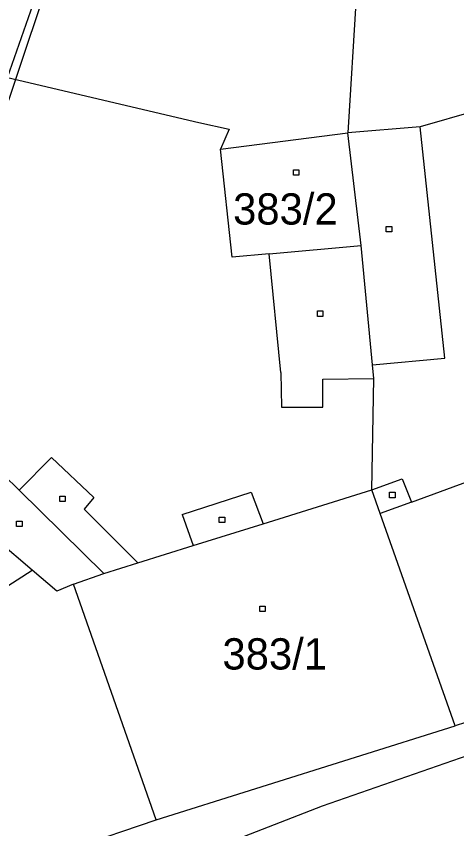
# Model space of a CAD drawing. Extents: x -711879 to -711361, y -1048782 to -1048177.
# Drawn here: x -711623.84 to -711599.87, y -1048524.94 to -1048480.75 of the extents above; entities that cross this region are included whole.
import ezdxf

# ---------------------------------------------------------------- set-up
doc = ezdxf.new("R2010")
doc.units = 0
for name, color, linetype in [('kresba', 7, 'Continuous'), ('Vrstva 1', 7, 'Continuous'), ('Vrstva 15', 7, 'Continuous'), ('Vrstva 2', 7, 'Continuous'), ('Vrstva 25', 7, 'Continuous'), ('Vrstva 46', 7, 'Continuous')]:
    doc.layers.add(name, color=color, linetype=linetype)

msp = doc.modelspace()

# ---------------------------------------------------------------- linework, layer by layer
at = {"layer": 'kresba'}
msp.add_line((-711627.89, -1048496.13), (-711612.41, -1048450.08), dxfattribs=at)
at = {"layer": 'Vrstva 1'}
for p, q in [((-711624.32, -1048484.08), (-711615.16, -1048458.11)), ((-711604.27, -1048461.61), (-711605.79, -1048487.1)), ((-711624.32, -1048484.08), (-711613.91, -1048486.53)), ((-711593.36, -1048484.32), (-711601.86, -1048486.76)), ((-711613.91, -1048486.53), (-711612.25, -1048486.89)), ((-711612.25, -1048486.89), (-711612.73, -1048487.98)), ((-711601.86, -1048486.76), (-711605.79, -1048487.1)), ((-711612.73, -1048487.98), (-711605.79, -1048487.1)), ((-711605.07, -1048493.22), (-711605.79, -1048487.1)), ((-711612.1, -1048493.86), (-711612.73, -1048487.98)), ((-711604.45, -1048499.71), (-711605.07, -1048493.22)), ((-711610.08, -1048493.68), (-711612.1, -1048493.86)), ((-711609.44, -1048500.12), (-711610.08, -1048493.68)), ((-711604.38, -1048500.46), (-711604.45, -1048499.71)), ((-711609.44, -1048500.12), (-711609.41, -1048502.02)), ((-711607.15, -1048500.49), (-711604.38, -1048500.46)), ((-711607.15, -1048502.02), (-711607.15, -1048500.49)), ((-711604.49, -1048506.5), (-711604.38, -1048500.46)), ((-711609.41, -1048502.02), (-711607.15, -1048502.02)), ((-711622.98, -1048510.87), (-711629.99, -1048504.96)), ((-711604.03, -1048507.8), (-711604.49, -1048506.5)), ((-711599.96, -1048519.34), (-711604.03, -1048507.8)), ((-711621.63, -1048512.01), (-711622.98, -1048510.87)), ((-711620.72, -1048511.64), (-711621.63, -1048512.01)), ((-711616.23, -1048524.45), (-711620.72, -1048511.64)), ((-711595.87, -1048518.02), (-711599.96, -1048519.34)), ((-711616.23, -1048524.45), (-711599.96, -1048519.34)), ((-711628.1, -1048528.47), (-711616.23, -1048524.45))]:
    msp.add_line(p, q, dxfattribs=at)
at = {"layer": 'Vrstva 2'}
for p, q in [((-711600.52, -1048499.34), (-711601.86, -1048486.76)), ((-711610.08, -1048493.68), (-711605.07, -1048493.22)), ((-711604.45, -1048499.71), (-711600.52, -1048499.34)), ((-711602.33, -1048507.17), (-711591.93, -1048503.34)), ((-711623.68, -1048506.53), (-711621.92, -1048504.75)), ((-711621.92, -1048504.75), (-711619.61, -1048506.92)), ((-711624.54, -1048505.69), (-711623.68, -1048506.53)), ((-711604.49, -1048506.5), (-711602.85, -1048505.91)), ((-711602.85, -1048505.91), (-711602.33, -1048507.17)), ((-711623.68, -1048506.53), (-711619.07, -1048511.05)), ((-711614.82, -1048507.85), (-711611.06, -1048506.63)), ((-711611.06, -1048506.63), (-711610.41, -1048508.35)), ((-711610.41, -1048508.35), (-711604.49, -1048506.5)), ((-711619.61, -1048506.92), (-711620.14, -1048507.56)), ((-711602.33, -1048507.17), (-711604.03, -1048507.8)), ((-711620.14, -1048507.56), (-711617.23, -1048510.48)), ((-711614.82, -1048507.85), (-711614.22, -1048509.54)), ((-711614.22, -1048509.54), (-711610.41, -1048508.35)), ((-711617.23, -1048510.48), (-711614.22, -1048509.54)), ((-711625.27, -1048512.34), (-711622.98, -1048510.87)), ((-711619.07, -1048511.05), (-711617.23, -1048510.48)), ((-711620.72, -1048511.64), (-711619.07, -1048511.05)), ((-711607.17, -1048523.7), (-711581.77, -1048514.86)), ((-711627.29, -1048531.47), (-711607.17, -1048523.7))]:
    msp.add_line(p, q, dxfattribs=at)
at = {"layer": 'Vrstva 25'}
for p, q in [((-711608.76, -1048489.1), (-711608.46, -1048489.1)), ((-711608.76, -1048489.4), (-711608.76, -1048489.1)), ((-711608.46, -1048489.1), (-711608.46, -1048489.4)), ((-711608.46, -1048489.4), (-711608.76, -1048489.4)), ((-711603.71, -1048492.18), (-711603.41, -1048492.18)), ((-711603.71, -1048492.48), (-711603.71, -1048492.18)), ((-711603.41, -1048492.18), (-711603.41, -1048492.48)), ((-711603.41, -1048492.48), (-711603.71, -1048492.48)), ((-711607.45, -1048496.78), (-711607.15, -1048496.78)), ((-711607.45, -1048497.08), (-711607.45, -1048496.78)), ((-711607.15, -1048497.08), (-711607.45, -1048497.08)), ((-711607.15, -1048496.78), (-711607.15, -1048497.08)), ((-711621.47, -1048506.85), (-711621.17, -1048506.85)), ((-711621.47, -1048507.15), (-711621.47, -1048506.85)), ((-711621.17, -1048506.85), (-711621.17, -1048507.15)), ((-711603.53, -1048506.64), (-711603.23, -1048506.64)), ((-711603.53, -1048506.94), (-711603.53, -1048506.64)), ((-711603.23, -1048506.64), (-711603.23, -1048506.94)), ((-711621.17, -1048507.15), (-711621.47, -1048507.15)), ((-711603.23, -1048506.94), (-711603.53, -1048506.94)), ((-711623.82, -1048508.21), (-711623.52, -1048508.21)), ((-711623.82, -1048508.51), (-711623.82, -1048508.21)), ((-711623.52, -1048508.21), (-711623.52, -1048508.51)), ((-711612.79, -1048507.99), (-711612.49, -1048507.99)), ((-711612.79, -1048508.29), (-711612.79, -1048507.99)), ((-711612.49, -1048507.99), (-711612.49, -1048508.29)), ((-711623.52, -1048508.51), (-711623.82, -1048508.51)), ((-711612.49, -1048508.29), (-711612.79, -1048508.29)), ((-711610.59, -1048512.83), (-711610.29, -1048512.83)), ((-711610.59, -1048513.13), (-711610.59, -1048512.83)), ((-711610.29, -1048512.83), (-711610.29, -1048513.13)), ((-711610.29, -1048513.13), (-711610.59, -1048513.13))]:
    msp.add_line(p, q, dxfattribs=at)
at = {"layer": 'Vrstva 46'}
for p, q in [((-711613.91, -1048486.53), (-711613.91, -1048486.53)), ((-711605.79, -1048487.1), (-711605.79, -1048487.1)), ((-711612.73, -1048487.98), (-711612.73, -1048487.98)), ((-711612.1, -1048493.86), (-711612.1, -1048493.86)), ((-711610.08, -1048493.68), (-711610.08, -1048493.68)), ((-711609.44, -1048500.12), (-711609.44, -1048500.12)), ((-711619.07, -1048511.05), (-711619.07, -1048511.05)), ((-711620.72, -1048511.64), (-711620.72, -1048511.64))]:
    msp.add_line(p, q, dxfattribs=at)

# ---------------------------------------------------------------- texts
at = {"layer": 'Vrstva 15'}
for s, p in [('383/2', (-711612.04, -1048492.08)), ('383/1', (-711612.62, -1048516.28))]:
    msp.add_text(s, height=1.7, dxfattribs=at).set_placement(p)

doc.saveas('drawing.dxf')
